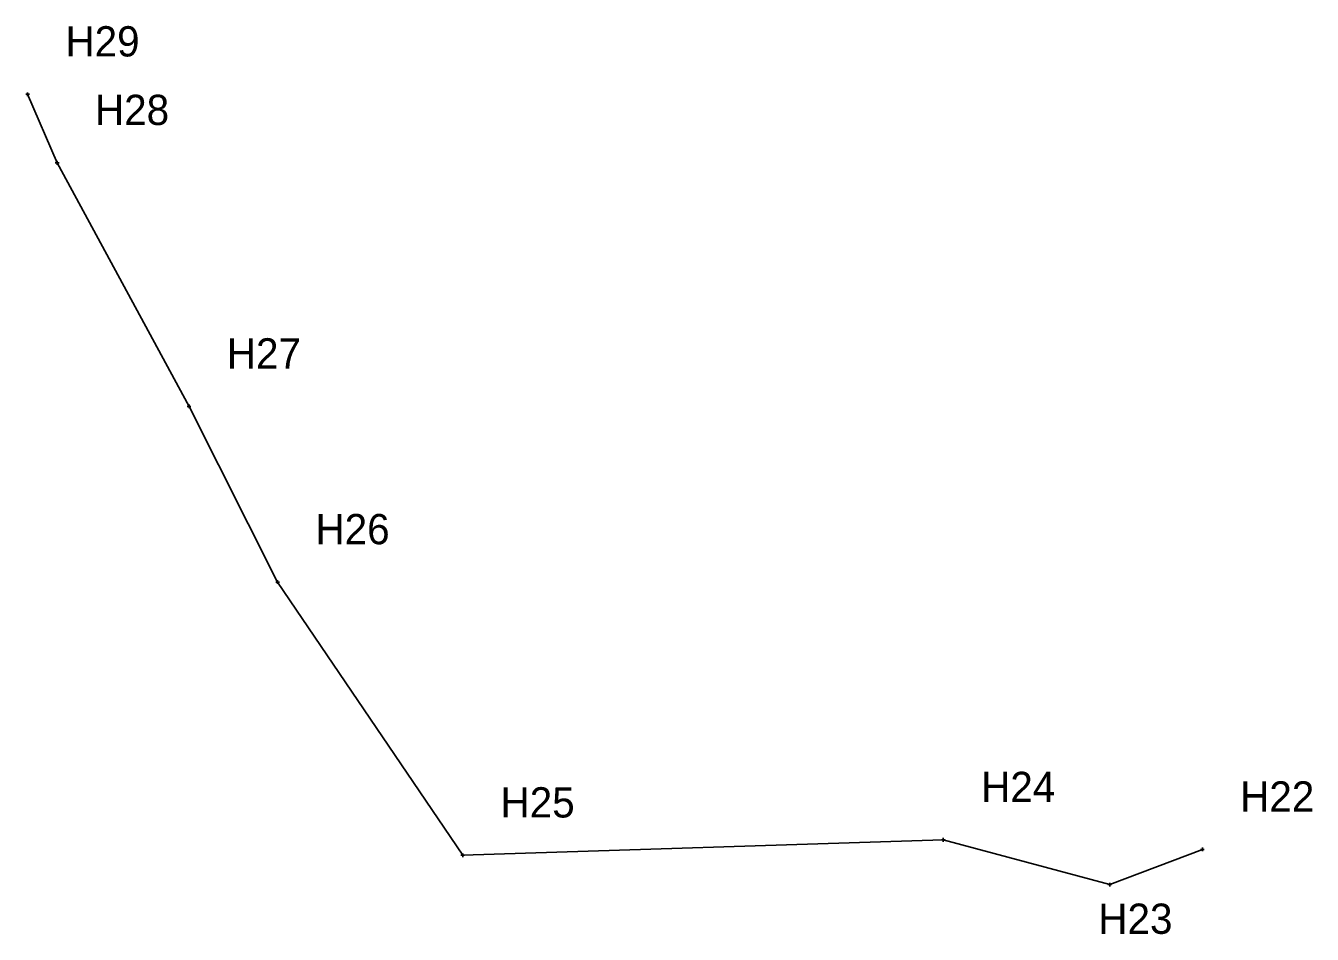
# Model space of a CAD drawing. Extents: x 1727245 to 1729607, y 652704 to 655271.
# Drawn here: x 1727963.5 to 1728133.7, y 653771.6 to 653891.7 of the extents above; entities that cross this region are included whole.
import ezdxf

# ---------------------------------------------------------------- set-up
doc = ezdxf.new("R2010")
doc.units = 0
for name, color, linetype in [('SURVEY - DRAINAGE - Storm Sewer', 7, 'Continuous'), ('SURVEY - DRAINAGE - Storm Sewer - Points - Locators', 7, 'Continuous'), ('SURVEY - DRAINAGE - Storm Sewer - Points - Numbers', 7, 'Continuous')]:
    doc.layers.add(name, color=color, linetype=linetype)

msp = doc.modelspace()

# ---------------------------------------------------------------- linework, layer by layer
at = {"layer": 'SURVEY - DRAINAGE - Storm Sewer'}
for p, q in [((1727963.75, 653882.63), (1727967.66, 653873.57)), ((1727967.66, 653873.57), (1727985.1, 653841.38)), ((1727985.1, 653841.38), (1727996.83, 653818.15)), ((1727996.83, 653818.15), (1728021.31, 653782.03)), ((1728021.31, 653782.03), (1728084.89, 653784.07)), ((1728084.89, 653784.07), (1728106.91, 653778.16)), ((1728106.91, 653778.16), (1728119.16, 653782.81))]:
    msp.add_line(p, q, dxfattribs=at)
at = {"layer": 'SURVEY - DRAINAGE - Storm Sewer - Points - Locators'}
for p, q in [((1727964, 653882.63), (1727963.5, 653882.63)), ((1727963.75, 653882.38), (1727963.75, 653882.88)), ((1727963.75, 653882.63), (1727963.75, 653882.63)), ((1727963.75, 653882.63), (1727963.75, 653882.63)), ((1727967.91, 653873.57), (1727967.41, 653873.57)), ((1727967.66, 653873.32), (1727967.66, 653873.82)), ((1727967.66, 653873.57), (1727967.66, 653873.57)), ((1727967.66, 653873.57), (1727967.66, 653873.57)), ((1727985.35, 653841.38), (1727984.85, 653841.38)), ((1727985.1, 653841.13), (1727985.1, 653841.63)), ((1727985.1, 653841.38), (1727985.1, 653841.38)), ((1727985.1, 653841.38), (1727985.1, 653841.38)), ((1727997.08, 653818.15), (1727996.58, 653818.15)), ((1727996.83, 653817.9), (1727996.83, 653818.4)), ((1727996.83, 653818.15), (1727996.83, 653818.15)), ((1727996.83, 653818.15), (1727996.83, 653818.15)), ((1728085.14, 653784.07), (1728084.64, 653784.07)), ((1728084.89, 653783.82), (1728084.89, 653784.32)), ((1728084.89, 653784.07), (1728084.89, 653784.07)), ((1728084.89, 653784.07), (1728084.89, 653784.07)), ((1728021.31, 653781.78), (1728021.31, 653782.28)), ((1728119.41, 653782.81), (1728118.91, 653782.81)), ((1728119.16, 653782.56), (1728119.16, 653783.06)), ((1728119.16, 653782.81), (1728119.16, 653782.81)), ((1728119.16, 653782.81), (1728119.16, 653782.81)), ((1728021.56, 653782.03), (1728021.06, 653782.03)), ((1728021.31, 653782.03), (1728021.31, 653782.03)), ((1728021.31, 653782.03), (1728021.31, 653782.03)), ((1728107.16, 653778.16), (1728106.66, 653778.16)), ((1728106.91, 653777.91), (1728106.91, 653778.41)), ((1728106.91, 653778.16), (1728106.91, 653778.16)), ((1728106.91, 653778.16), (1728106.91, 653778.16))]:
    msp.add_line(p, q, dxfattribs=at)

# ---------------------------------------------------------------- texts
at = {"layer": 'SURVEY - DRAINAGE - Storm Sewer - Points - Numbers'}
for s, p in [('H29', (1727968.75, 653887.63)), ('H28', (1727972.66, 653878.57)), ('H27', (1727990.1, 653846.38)), ('H26', (1728001.83, 653823.15)), ('H24', (1728089.89, 653789.07)), ('H25', (1728026.31, 653787.03)), ('H22', (1728124.16, 653787.81)), ('H23', (1728105.4, 653771.65))]:
    msp.add_text(s, height=4, dxfattribs=at).set_placement(p)

doc.saveas('drawing.dxf')
